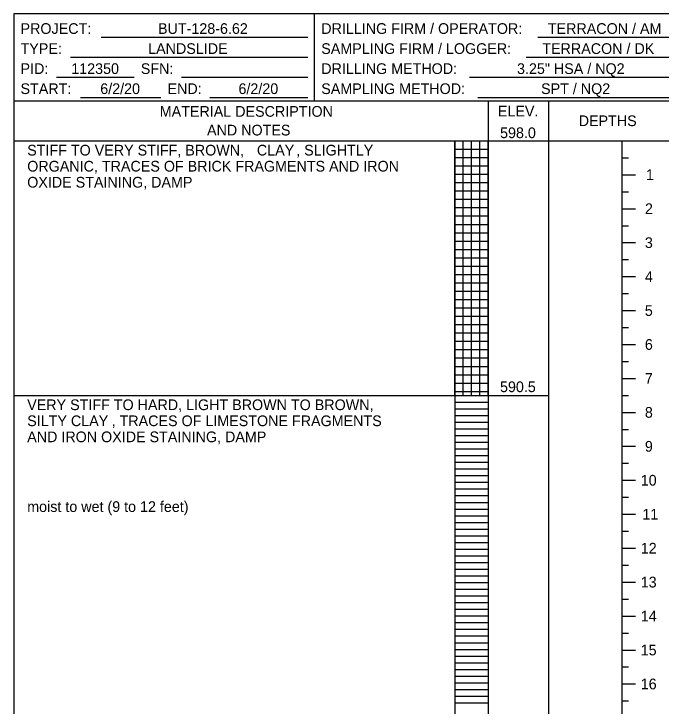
# Model space of a CAD drawing. Extents: x 0 to 0.833, y -0.254 to 0.608.
# Drawn here: x 0 to 0.4036, y 0.1767 to 0.6083 of the extents above; entities that cross this region are included whole.
import ezdxf

# ---------------------------------------------------------------- set-up
doc = ezdxf.new("R2010")
doc.units = 0

msp = doc.modelspace()

# ---------------------------------------------------------------- linework, layer by layer
msp.add_lwpolyline([(0, -0.25414), (0.83333, -0.25414), (0.83333, 0.60833), (0, 0.60833)], close=True)
for points in [[(0.1875, 0.55417), (0.1875, 0.60833)], [(0.05444, 0.59375), (0.18333, 0.59375)], [(0.32667, 0.59375), (0.4125, 0.59375)], [(0.03542, 0.58125), (0.18333, 0.58125)], [(0.31944, 0.58125), (0.4125, 0.58125)], [(0.02653, 0.56875), (0.075, 0.56875)], [(0.10458, 0.56875), (0.18333, 0.56875)], [(0.28403, 0.56875), (0.4125, 0.56875)], [(0, 0.55417), (0.83333, 0.55417)], [(0, 0.55417), (0.83333, 0.55417)], [(0, 0.55417), (0.83333, 0.55417)], [(0, 0.55417), (0.83333, 0.55417)], [(0, 0.55417), (0.83333, 0.55417)], [(0.04153, 0.55625), (0.09167, 0.55625)], [(0.12222, 0.55625), (0.18333, 0.55625)], [(0.2893, 0.55625), (0.4125, 0.55625)], [(0.29583, 0.55417), (0.29583, -0.21167)], [(0.29583, 0.55417), (0.29583, -0.21167)], [(0.33333, 0.55417), (0.33333, -0.21167)], [(0.33333, 0.55417), (0.33333, -0.21167)], [(0, 0.52917), (0.83333, 0.52917)], [(0, 0.52917), (0.83333, 0.52917)], [(0, 0.52917), (0.83333, 0.52917)], [(0, 0.52917), (0.83333, 0.52917)], [(0, 0.52917), (0.83333, 0.52917)], [(0.275, 0.52917), (0.29583, 0.52917)], [(0.275, 0.37042), (0.275, 0.52917)], [(0.275, 0.52917), (0.275, 0.37042)], [(0.275, 0.52917), (0.275, -0.21167)], [(0.28021, 0.37042), (0.28021, 0.52917)], [(0.28542, 0.37042), (0.28542, 0.52917)], [(0.29062, 0.37042), (0.29062, 0.52917)], [(0.29583, 0.37042), (0.29583, 0.52917)], [(0.29583, 0.52917), (0.33333, 0.52917)], [(0.37917, 0.52917), (0.37917, -0.21167)], [(0.275, 0.52396), (0.29583, 0.52396)], [(0.275, 0.51875), (0.29583, 0.51875)], [(0.37917, 0.51858), (0.38333, 0.51858)], [(0.275, 0.51354), (0.29583, 0.51354)], [(0.275, 0.50833), (0.29583, 0.50833)], [(0.37917, 0.508), (0.3875, 0.508)], [(0.37917, 0.508), (0.38333, 0.508)], [(0.275, 0.50312), (0.29583, 0.50312)], [(0.275, 0.49792), (0.29583, 0.49792)], [(0.37917, 0.49742), (0.38333, 0.49742)], [(0.275, 0.49271), (0.29583, 0.49271)], [(0.275, 0.4875), (0.29583, 0.4875)], [(0.37917, 0.48683), (0.3875, 0.48683)], [(0.37917, 0.48683), (0.38333, 0.48683)], [(0.275, 0.48229), (0.29583, 0.48229)], [(0.275, 0.47708), (0.29583, 0.47708)], [(0.37917, 0.47625), (0.38333, 0.47625)], [(0.275, 0.47187), (0.29583, 0.47187)], [(0.275, 0.46667), (0.29583, 0.46667)], [(0.37917, 0.46567), (0.3875, 0.46567)], [(0.37917, 0.46567), (0.38333, 0.46567)], [(0.275, 0.46146), (0.29583, 0.46146)], [(0.275, 0.45625), (0.29583, 0.45625)], [(0.37917, 0.45508), (0.38333, 0.45508)], [(0.275, 0.45104), (0.29583, 0.45104)], [(0.275, 0.44583), (0.29583, 0.44583)], [(0.275, 0.44062), (0.29583, 0.44062)], [(0.37917, 0.4445), (0.3875, 0.4445)], [(0.37917, 0.4445), (0.38333, 0.4445)], [(0.275, 0.43542), (0.29583, 0.43542)], [(0.37917, 0.43392), (0.38333, 0.43392)], [(0.275, 0.43021), (0.29583, 0.43021)], [(0.275, 0.425), (0.29583, 0.425)], [(0.37917, 0.42333), (0.3875, 0.42333)], [(0.37917, 0.42333), (0.38333, 0.42333)], [(0.275, 0.41979), (0.29583, 0.41979)], [(0.275, 0.41458), (0.29583, 0.41458)], [(0.37917, 0.41275), (0.38333, 0.41275)], [(0.275, 0.40937), (0.29583, 0.40937)], [(0.275, 0.40417), (0.29583, 0.40417)], [(0.37917, 0.40217), (0.3875, 0.40217)], [(0.37917, 0.40217), (0.38333, 0.40217)], [(0.275, 0.39896), (0.29583, 0.39896)], [(0.275, 0.39375), (0.29583, 0.39375)], [(0.275, 0.38854), (0.29583, 0.38854)], [(0.37917, 0.39158), (0.38333, 0.39158)], [(0.275, 0.38333), (0.29583, 0.38333)], [(0.37917, 0.381), (0.3875, 0.381)], [(0.37917, 0.381), (0.38333, 0.381)], [(0.275, 0.37812), (0.29583, 0.37812)], [(0.275, 0.37292), (0.29583, 0.37292)], [(0, 0.37042), (0.275, 0.37042)], [(0.275, 0.37042), (0.29583, 0.37042)], [(0.275, 0.37042), (0.29583, 0.37042)], [(0.275, 0.37042), (0.275, 0.10583)], [(0.29583, 0.37042), (0.33333, 0.37042)], [(0.37917, 0.37042), (0.38333, 0.37042)], [(0.275, 0.36625), (0.29583, 0.36625)], [(0.275, 0.36208), (0.29583, 0.36208)], [(0.37917, 0.35983), (0.3875, 0.35983)], [(0.37917, 0.35983), (0.38333, 0.35983)], [(0.275, 0.35792), (0.29583, 0.35792)], [(0.275, 0.35375), (0.29583, 0.35375)], [(0.275, 0.34958), (0.29583, 0.34958)], [(0.275, 0.34542), (0.29583, 0.34542)], [(0.37917, 0.34925), (0.38333, 0.34925)], [(0.275, 0.34125), (0.29583, 0.34125)], [(0.275, 0.33708), (0.29583, 0.33708)], [(0.37917, 0.33867), (0.3875, 0.33867)], [(0.37917, 0.33867), (0.38333, 0.33867)], [(0.275, 0.33292), (0.29583, 0.33292)], [(0.275, 0.32875), (0.29583, 0.32875)], [(0.37917, 0.32808), (0.38333, 0.32808)], [(0.275, 0.32458), (0.29583, 0.32458)], [(0.275, 0.32042), (0.29583, 0.32042)], [(0.275, 0.31625), (0.29583, 0.31625)], [(0.37917, 0.3175), (0.3875, 0.3175)], [(0.37917, 0.3175), (0.38333, 0.3175)], [(0.275, 0.31208), (0.29583, 0.31208)], [(0.275, 0.30792), (0.29583, 0.30792)], [(0.37917, 0.30692), (0.38333, 0.30692)], [(0.275, 0.30375), (0.29583, 0.30375)], [(0.275, 0.29958), (0.29583, 0.29958)], [(0.275, 0.29542), (0.29583, 0.29542)], [(0.37917, 0.29633), (0.3875, 0.29633)], [(0.37917, 0.29633), (0.38333, 0.29633)], [(0.275, 0.29125), (0.29583, 0.29125)], [(0.275, 0.28708), (0.29583, 0.28708)], [(0.37917, 0.28575), (0.38333, 0.28575)], [(0.275, 0.28292), (0.29583, 0.28292)], [(0.275, 0.27875), (0.29583, 0.27875)], [(0.275, 0.27458), (0.29583, 0.27458)], [(0.37917, 0.27517), (0.3875, 0.27517)], [(0.37917, 0.27517), (0.38333, 0.27517)], [(0.275, 0.27042), (0.29583, 0.27042)], [(0.275, 0.26625), (0.29583, 0.26625)], [(0.37917, 0.26458), (0.38333, 0.26458)], [(0.275, 0.26208), (0.29583, 0.26208)], [(0.275, 0.25792), (0.29583, 0.25792)], [(0.275, 0.25375), (0.29583, 0.25375)], [(0.37917, 0.254), (0.3875, 0.254)], [(0.37917, 0.254), (0.38333, 0.254)], [(0.275, 0.24958), (0.29583, 0.24958)], [(0.275, 0.24542), (0.29583, 0.24542)], [(0.37917, 0.24342), (0.38333, 0.24342)], [(0.275, 0.24125), (0.29583, 0.24125)], [(0.275, 0.23708), (0.29583, 0.23708)], [(0.275, 0.23292), (0.29583, 0.23292)], [(0.37917, 0.23283), (0.3875, 0.23283)], [(0.37917, 0.23283), (0.38333, 0.23283)], [(0.275, 0.22875), (0.29583, 0.22875)], [(0.275, 0.22458), (0.29583, 0.22458)], [(0.275, 0.22042), (0.29583, 0.22042)], [(0.37917, 0.22225), (0.38333, 0.22225)], [(0.275, 0.21625), (0.29583, 0.21625)], [(0.275, 0.21208), (0.29583, 0.21208)], [(0.37917, 0.21167), (0.3875, 0.21167)], [(0.37917, 0.21167), (0.38333, 0.21167)], [(0.275, 0.20792), (0.29583, 0.20792)], [(0.275, 0.20375), (0.29583, 0.20375)], [(0.275, 0.19958), (0.29583, 0.19958)], [(0.37917, 0.20108), (0.38333, 0.20108)], [(0.275, 0.19542), (0.29583, 0.19542)], [(0.275, 0.19125), (0.29583, 0.19125)], [(0.37917, 0.1905), (0.3875, 0.1905)], [(0.37917, 0.1905), (0.38333, 0.1905)], [(0.275, 0.18708), (0.29583, 0.18708)], [(0.275, 0.18292), (0.29583, 0.18292)], [(0.275, 0.17875), (0.29583, 0.17875)], [(0.37917, 0.17992), (0.38333, 0.17992)]]:
    msp.add_lwpolyline(points)

# ---------------------------------------------------------------- texts
for s, height, p in [('PROJECT:', 0.006667, (0.00417, 0.59583)), ('BUT-128-6.62', 0.0066667, (0.08989, 0.59583)), ('DRILLING FIRM / OPERATOR:', 0.0066667, (0.19167, 0.59583)), ('TERRACON / AM', 0.0066667, (0.33293, 0.59583)), ('TYPE:', 0.006667, (0.00417, 0.58333)), ('LANDSLIDE', 0.006667, (0.08374, 0.58333)), ('SAMPLING FIRM / LOGGER:', 0.0066667, (0.19167, 0.58333)), ('TERRACON / DK', 0.0066667, (0.32949, 0.58333)), ('PID:', 0.006667, (0.00417, 0.57083)), ('112350', 0.006667, (0.0358, 0.57083)), ('SFN:', 0.006667, (0.07917, 0.57083)), ('DRILLING METHOD:', 0.0066667, (0.19167, 0.57083)), ('3.25" HSA / NQ2', 0.0066667, (0.31373, 0.57083)), ('START:', 0.006667, (0.00417, 0.55833)), ('6/2/20', 0.006667, (0.05388, 0.55833)), ('END:', 0.006667, (0.09583, 0.55833)), ('6/2/20', 0.006667, (0.14006, 0.55833)), ('SAMPLING METHOD:', 0.0066667, (0.19167, 0.55833)), ('SPT / NQ2', 0.006667, (0.32872, 0.55833)), ('MATERIAL DESCRIPTION', 0.0066667, (0.09097, 0.54417)), ('ELEV.', 0.006667, (0.30179, 0.54437)), ('DEPTHS', 0.006667, (0.35218, 0.53833)), ('AND NOTES', 0.006667, (0.12044, 0.5325)), ('598.0', 0.006667, (0.30316, 0.53083)), ('STIFF TO VERY STIFF, BROWN, ', 0.0066667, (0.00833, 0.52)), ('CLAY', 0.006667, (0.15153, 0.52)), (', SLIGHTLY', 0.006667, (0.17604, 0.52)), ('ORGANIC, TRACES OF BRICK FRAGMENTS AND IRON', 0.0066667, (0.00833, 0.51)), ('1', 0.00667, (0.3941, 0.50467)), ('OXIDE STAINING, DAMP', 0.0066667, (0.00833, 0.5)), ('2', 0.00667, (0.39349, 0.4835)), ('3', 0.00667, (0.39345, 0.46233)), ('4', 0.00667, (0.39347, 0.44117)), ('5', 0.00667, (0.39343, 0.42)), ('6', 0.00667, (0.39345, 0.39883)), ('7', 0.00667, (0.39345, 0.37767)), ('590.5', 0.006667, (0.30312, 0.37246)), ('VERY STIFF TO HARD, LIGHT BROWN TO BROWN,', 0.0066667, (0.00833, 0.36125)), ('8', 0.00667, (0.39345, 0.3565)), ('SILTY CLAY', 0.006667, (0.00833, 0.35125)), (', TRACES OF LIMESTONE FRAGMENTS', 0.0066667, (0.06097, 0.35125)), ('AND IRON OXIDE STAINING, DAMP', 0.0066667, (0.00833, 0.34125)), ('9', 0.00667, (0.39345, 0.33533)), ('10', 0.006667, (0.39088, 0.31417)), ('moist to wet (9 to 12 feet)', 0.0066667, (0.00833, 0.29775)), ('11', 0.006667, (0.39186, 0.293)), ('12', 0.006667, (0.3909, 0.27183)), ('13', 0.006667, (0.39087, 0.25067)), ('14', 0.006667, (0.39088, 0.2295)), ('15', 0.006667, (0.39084, 0.20833)), ('16', 0.006667, (0.39087, 0.18717))]:
    msp.add_text(s, height=height).set_placement(p)

doc.saveas('drawing.dxf')
